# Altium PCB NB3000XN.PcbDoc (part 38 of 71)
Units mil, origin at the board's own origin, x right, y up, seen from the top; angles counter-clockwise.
Board outline 9527.56 x 6929.77 mil, 6 copper layers (Top Layer, GND+SHIELD, MidLayer1, MidLayer2, P2 - 3V3+5V0, Bottom Layer), stack 62.375 mil thick; 832 components, 1027 nets, 4655 pads, 4981 vias.
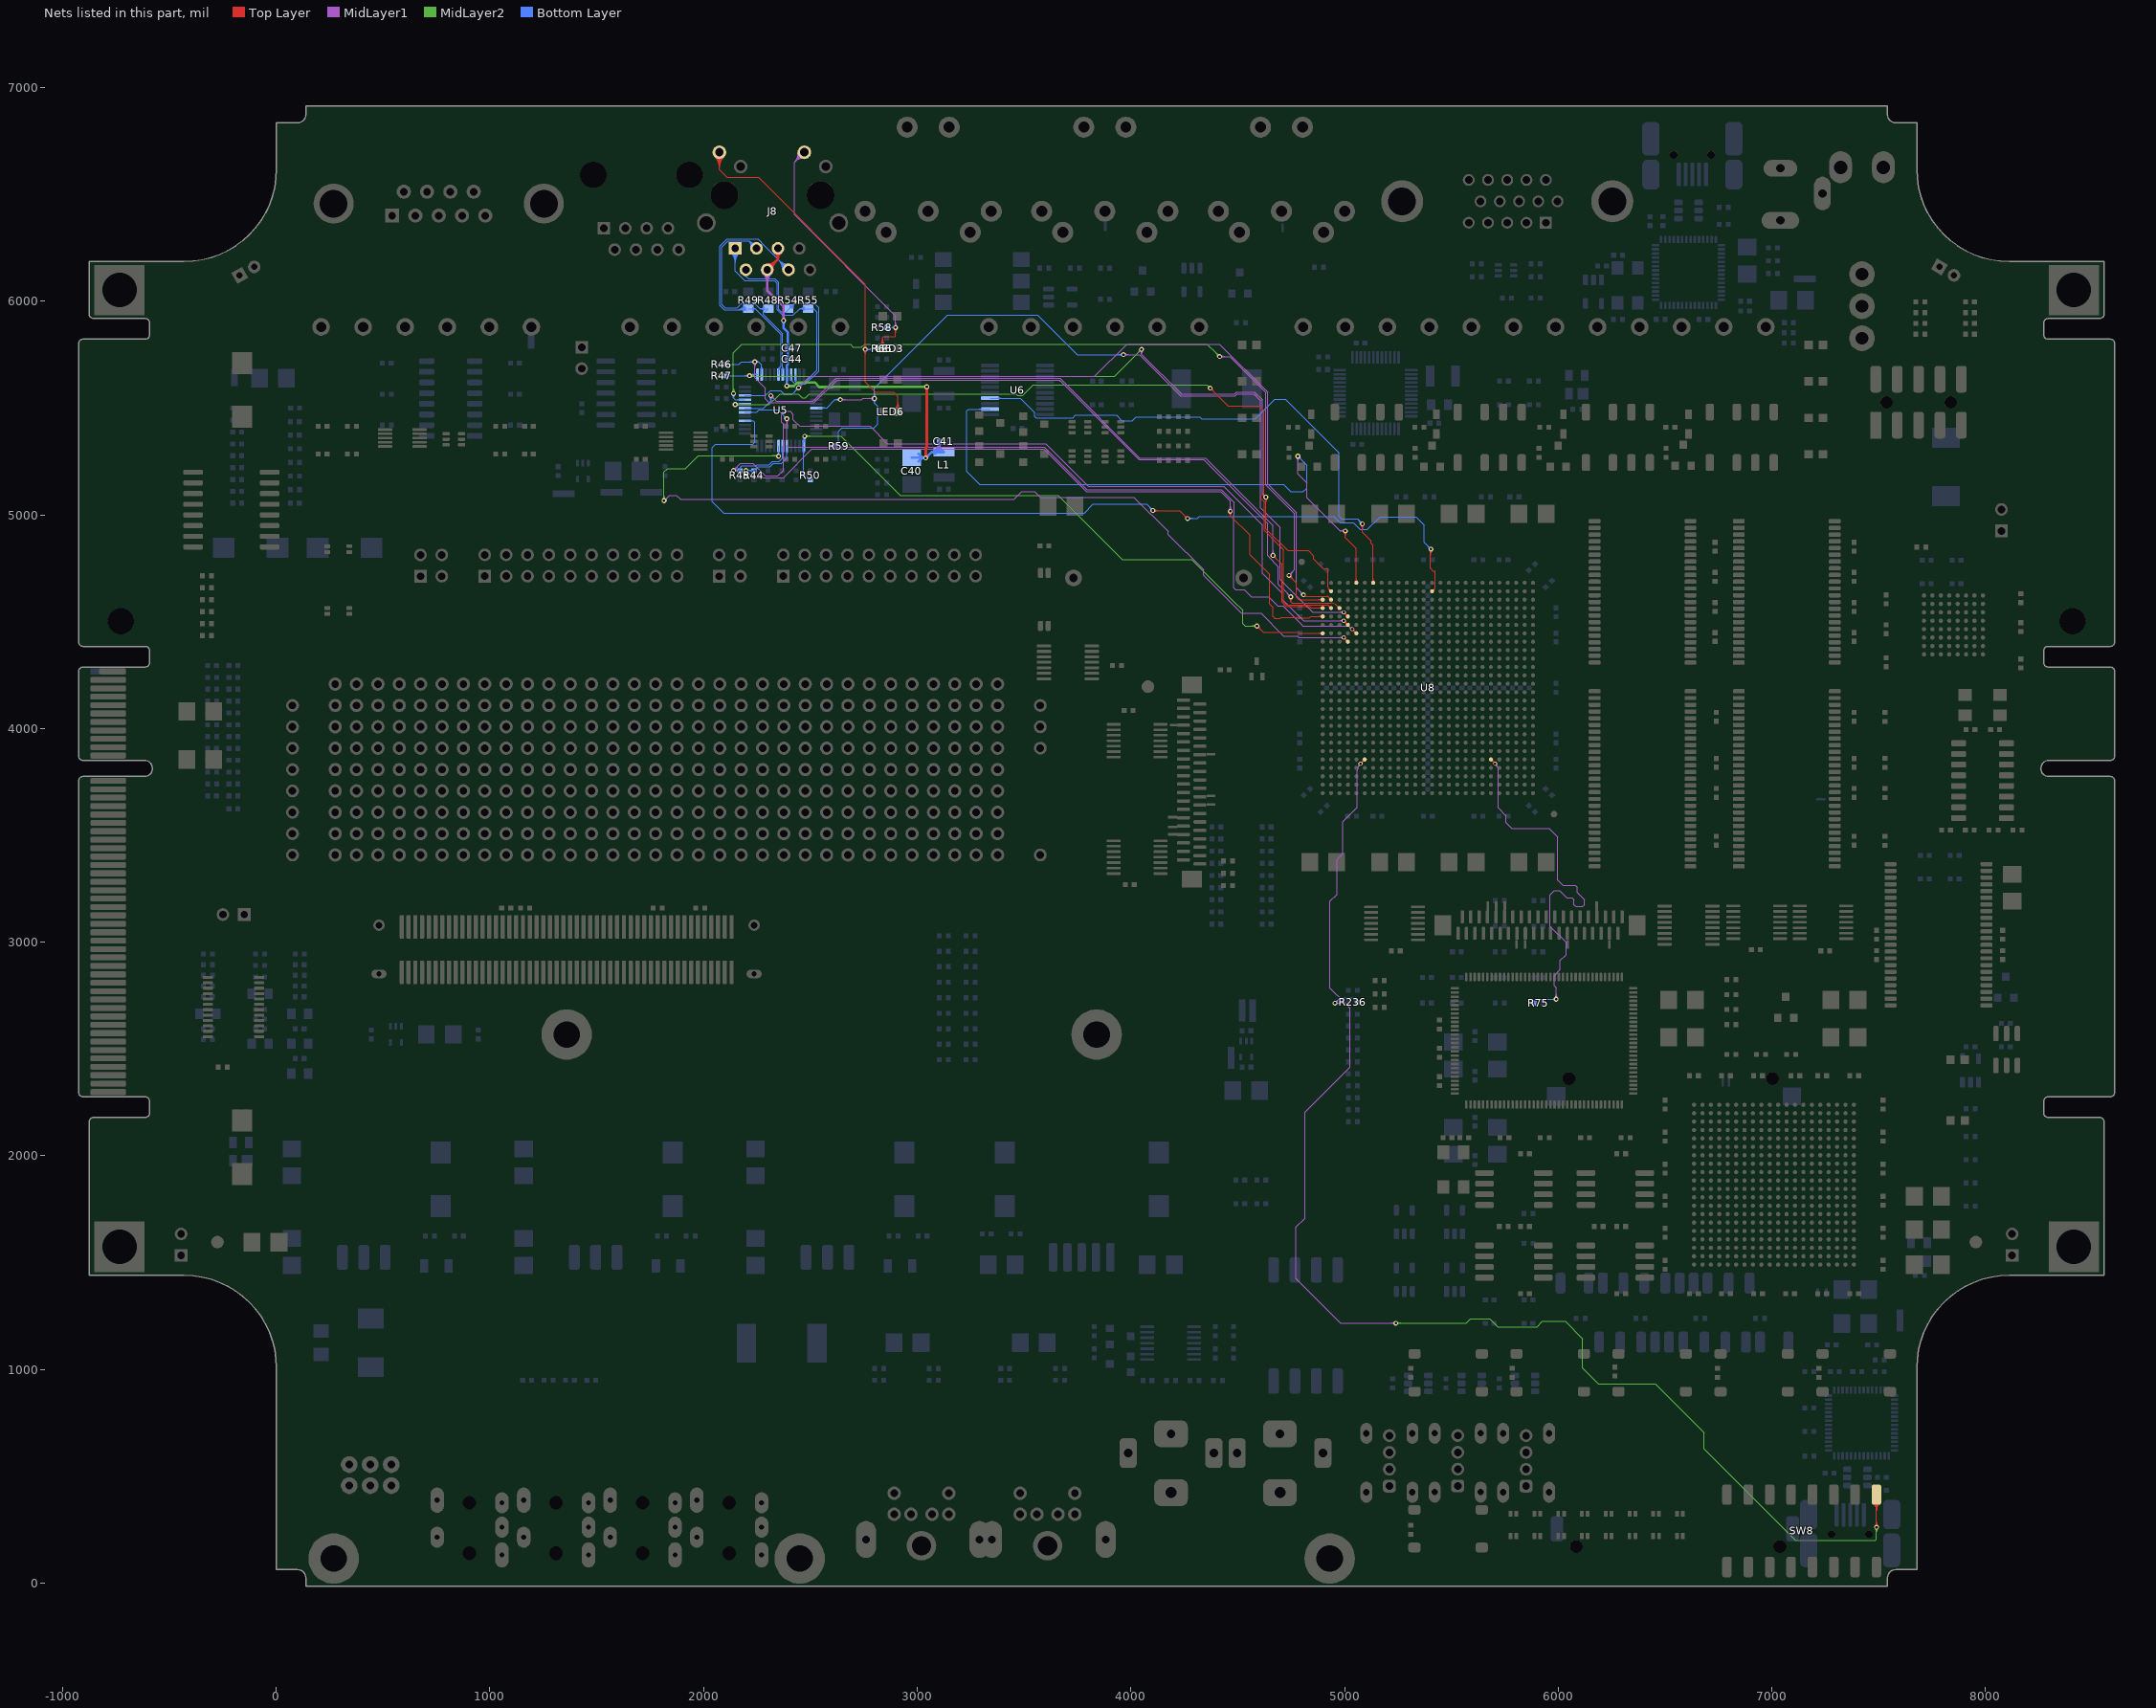
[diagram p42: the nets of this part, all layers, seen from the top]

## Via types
v1: diameter 23, hole 11.81, Top Layer to Bottom Layer, 3672 vias
v2: diameter 26, hole 11.81, Top Layer to Bottom Layer, 461 vias
v3: diameter 19, hole 11.81, Top Layer to Bottom Layer, tented both sides, 396 vias
v4: diameter 23.62, hole 11.81, Top Layer to Bottom Layer, 288 vias
v5: diameter 20, hole 11.81, Top Layer to Bottom Layer, 91 vias
v6: diameter 23, hole 11.81, Top Layer to Bottom Layer, tented both sides, 50 vias
v7: diameter 31, hole 11.81, Top Layer to Bottom Layer, 15 vias
v8: diameter 27.56, hole 11.81, Top Layer to Bottom Layer, tented both sides, 4 vias
v9: diameter 29, hole 11.81, Top Layer to Bottom Layer, 3 vias
v10: diameter 21, hole 11.81, Top Layer to Bottom Layer, 1 vias

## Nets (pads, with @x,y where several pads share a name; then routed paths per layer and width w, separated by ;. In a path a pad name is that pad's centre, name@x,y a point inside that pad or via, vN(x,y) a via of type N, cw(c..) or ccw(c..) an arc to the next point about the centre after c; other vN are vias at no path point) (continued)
DIPSW.D7: R236.1 SW8.9 U8.AB6 | length 7106.8
  Top Layer w4: v3(5075.04,3835.67) U8.AB6@5094.72,3855.35 ; U8.AB6@5087.22,3855.35 cw(c5069.12,3855.35) 5081.92,3842.55 cw(c5094.72,3829.75) U8.AB6@5094.72,3847.85 ; U8.AB6@5087.38,3855.35 cw(c5069.66,3855.35) 5082.19,3842.82 cw(c5094.72,3830.29) U8.AB6@5094.72,3848.01 ; SW8.9@7475.69,374.19 cw(c7441.13,339.63) 7490,339.63 cw(c7538.87,339.63) SW8.9@7504.31,374.19 ; SW8.9@7478.51,377.02 cw(c7450.78,349.29) 7490,349.29 cw(c7529.22,349.29) SW8.9@7501.49,377.02 ; SW8.9@7481.34,379.85 cw(c7460.44,358.94) 7490,358.94 cw(c7519.56,358.94) SW8.9@7498.66,379.85 ; v1@7483.47,268.43 ccw(c7467.71,284.18) 7490,284.18 ; v1@7486.3,265.6 ccw(c7477.37,274.53) 7490,274.53 ; 7490,275.44 ccw(c7503.93,275.44) v1@7494.08,265.6 ; 7490,285.1 ccw(c7513.58,285.1) v1@7496.91,268.43 ; SW8.9@7490,414.29 7490,273.23 7490.19,273.04 v1(7490.19,261.71) ; 5087.84,3848.47 cw(c5075.04,3861.28) 5075.04,3843.17 ccw(c5075.04,3861.28) 5087.84,3848.47 ; 5087.84,3848.47 ccw(c5100.65,3835.67) 5082.54,3835.67 cw(c5100.65,3835.67) 5087.84,3848.47
  MidLayer1 w4: v1(4955,2715) 5002.23,2715 ; v1@4958.89,2711.11 cw(c4968.28,2701.72) 4968.28,2715 cw(c4968.28,2728.28) v1@4958.89,2718.89 ; v1@4961.72,2708.28 cw(c4977.93,2692.06) 4977.93,2715 cw(c4977.93,2737.93) v1@4961.72,2721.72 ; 5064.62,3820.81 ccw(c5092.66,3803.16) 5059.53,3802.99 5059.53,3718.62 5059.53,3670 5059.53,3660 5059.53,3630.7 4992.19,3563.35 4992.19,3413.69 4964.86,3386.36 4964.86,3224.71 4931.86,3191.71 4931.86,2785.37 5002.23,2715 ; v3@5067.65,3834.37 cw(c5049.82,3831.22) 5064.65,3820.84 cw(c5079.49,3810.45) v3@5076.34,3828.28 ; v1@5233.47,1209.99 ccw(c5217.26,1193.77) 5217.26,1216.71 ccw(c5217.26,1239.64) v1@5233.47,1223.43 ; v1@5236.3,1212.82 ccw(c5226.91,1203.43) 5226.91,1216.71 ccw(c5226.91,1229.99) v1@5236.3,1220.6 ; v1(5240.19,1216.71) 4981.86,1216.71 4773.52,1425.04 4773.52,1666.71 4815.19,1708.37 4815.19,2204.71 5025.52,2415.04 5025.52,2691.71 5002.23,2715
  MidLayer2 w4: v1(5240.19,1216.71) 5570.14,1216.71 5590.72,1237.29 5680.32,1237.29 5717.39,1200.21 5901.32,1200.21 5926.31,1225.21 6032.42,1225.21 6113.36,1144.27 6113.36,1007.23 6187.7,932.88 6193.46,932.88 6193.96,933.37 6370,933.37 ; v1@5244.08,1212.82 cw(c5253.47,1203.43) 5253.47,1216.71 cw(c5253.47,1229.99) v1@5244.08,1220.6 ; v1@5246.91,1209.99 cw(c5263.13,1193.77) 5263.13,1216.71 cw(c5263.13,1239.64) v1@5246.91,1223.43 ; 6370,933.71 6454.98,933.71 6683.77,704.91 6683.77,627.79 7111.52,200.04 7485.04,200.04 7490.19,205.19 v1(7490.19,261.71) ; v1@7484,254.5 cw(c7472.46,241.04) 7490.19,241.04 cw(c7507.92,241.04) v1@7496.38,254.5 ; v1@7486.61,257.53 cw(c7479.93,249.74) 7490.19,249.74 cw(c7500.45,249.74) v1@7493.77,257.53
  Bottom Layer w4: v1(4955,2715) 4980,2740 5040.27,2740 R236.1@5061.18,2719.09 ; v1@4955,2720.5 ccw(c4955,2733.78) 4964.39,2724.39 ccw(c4973.78,2715) v1@4960.5,2715 ; v1@4955,2724.5 ccw(c4955,2747.43) 4971.22,2731.22 ccw(c4987.43,2715) v1@4964.5,2715 ; 5044.43,2735.84 ccw(c5061.18,2752.59) R236.1@5061.18,2728.9 ; 5045.62,2734.65 cw(c5030.55,2719.58) R236.1@5051.86,2719.58 ; R236.1@5051.26,2729.01 ccw(c5061.18,2738.93) R236.1@5061.18,2724.9 ; R236.1@5052.45,2727.82 cw(c5044.21,2719.58) R236.1@5055.86,2719.58
DONE: R75.2 U8.AB21 | length 2109.8
  Top Layer w4: U8.AB21@5685.28,3847.85 cw(c5685.28,3829.75) 5698.08,3842.55 cw(c5710.88,3855.35) U8.AB21@5692.78,3855.35 ; U8.AB21@5685.28,3848.01 cw(c5685.28,3830.29) 5697.81,3842.82 cw(c5710.34,3855.35) U8.AB21@5692.62,3855.35 ; U8.AB21@5685.28,3855.35 v3(5704.96,3835.67) ; 5692.16,3848.47 cw(c5679.35,3835.67) 5697.46,3835.67 ccw(c5679.35,3835.67) 5692.16,3848.47 ; 5692.16,3848.47 ccw(c5704.96,3861.28) 5704.96,3843.17 cw(c5704.96,3861.28) 5692.16,3848.47
  MidLayer1 w4: v3@5703.66,3828.28 cw(c5700.51,3810.45) 5715.35,3820.84 cw(c5730.18,3831.22) v3@5712.35,3834.37 ; 5715.38,3820.81 cw(c5687.34,3803.16) 5720.47,3802.99 5720.47,3718.62 5720.47,3670 5720.47,3660 5720.47,3628.06 5756.52,3592 5756.52,3559.98 5783.13,3533.37 5956.86,3533.37 5998.52,3491.71 5998.52,3291.29 6023.1,3266.71 6080.86,3266.71 6089.19,3258.37 6089.19,3233.37 6123.52,3199.04 6123.52,3175.04 6115.19,3166.71 6081.86,3166.71 6073.52,3175.04 6073.52,3200.04 6065.19,3208.37 6040.19,3208.37 6006.86,3241.71 5981.86,3241.71 5962.52,3222.37 5962.52,3074.73 6037.81,2999.44 6037.81,2942.31 6009.19,2913.69 6009.19,2871.37 5981.86,2844.04 5981.86,2795 5990.19,2786.67 v1(5990.19,2733.37) ; v1@5983.47,2740.09 ccw(c5967.26,2756.31) 5990.19,2756.31 ccw(c6013.13,2756.31) v1@5996.91,2740.09 ; v1@5986.3,2737.26 ccw(c5976.91,2746.65) 5990.19,2746.65 ccw(c6003.47,2746.65) v1@5994.08,2737.26
  Bottom Layer w4: R75.2@5885.82,2716.71 R75.2@5885.82,2715 5904.19,2733.37 v1(5990.19,2733.37) ; R75.2@5885.82,2720.81 ccw(c5885.82,2734.84) R75.2@5895.74,2724.92 ; R75.2@5885.82,2724.81 ccw(c5885.82,2748.5) 5902.57,2731.75 ; R75.2@5891.14,2715.49 cw(c5902.79,2715.49) R75.2@5894.55,2723.73 ; R75.2@5895.14,2715.49 cw(c5916.45,2715.49) 5901.38,2730.56
ETH#.ACT_A: J8.9 LED6.1 R66.2 | length 2525.6
  Top Layer w4: J8.9@2052.85,6676.36 cw(c2001.82,6625.33) 2073.98,6625.33 cw(c2146.14,6625.33) J8.9@2095.12,6676.36 ; J8.9@2055.68,6679.18 cw(c2011.48,6634.99) 2073.98,6634.99 cw(c2136.49,6634.99) J8.9@2092.29,6679.18 ; J8.9@2058.51,6682.01 cw(c2021.14,6644.64) 2073.98,6644.64 cw(c2126.83,6644.64) J8.9@2089.46,6682.01 ; J8.9@2061.33,6684.84 cw(c2030.79,6654.3) 2073.98,6654.3 cw(c2117.17,6654.3) J8.9@2086.63,6684.84 ; J8.9@2064.16,6687.67 cw(c2040.45,6663.96) 2073.98,6663.96 cw(c2107.52,6663.96) J8.9@2083.81,6687.67 ; J8.9@2073.98,6697.49 2073.98,6616.02 2110,6580 2256.9,6580 2756.86,6080.04 v1(2756.86,5775.04) 2756.86,5623.14 2805,5575 2890,5575 2909.01,5555.99 2909.01,5509.15 ; v1@2750.14,5768.32 cw(c2733.92,5752.11) 2756.86,5752.11 cw(c2779.79,5752.11) v1@2763.57,5768.32 ; v1@2750.14,5781.76 ccw(c2733.92,5797.98) 2756.86,5797.98 ccw(c2779.79,5797.98) v1@2763.57,5781.76 ; v1@2752.97,5771.15 cw(c2743.58,5761.76) 2756.86,5761.76 cw(c2770.14,5761.76) v1@2760.75,5771.15 ; v1@2752.97,5778.93 ccw(c2743.58,5788.32) 2756.86,5788.32 ccw(c2770.14,5788.32) v1@2760.75,5778.93 ; LED6.1@2896.51,5495.97 ccw(c2866.32,5526.16) 2909.01,5526.16 ccw(c2951.71,5526.16) LED6.1@2921.52,5495.97 ; LED6.1@2899.34,5493.15 ccw(c2875.97,5516.51) 2909.01,5516.51 ccw(c2942.05,5516.51) LED6.1@2918.69,5493.15 ; LED6.1@2902.16,5490.32 ccw(c2885.63,5506.85) 2909.01,5506.85 ccw(c2932.39,5506.85) LED6.1@2915.86,5490.32
  Bottom Layer w4: v1(2756.86,5775.04) 2779.86,5775.04 2783.82,5779 R66.2@2813.82,5779 ; v1@2760.75,5771.15 cw(c2770.14,5761.76) 2770.14,5775.04 cw(c2770.14,5788.32) v1@2760.75,5778.93 ; v1@2763.57,5768.32 cw(c2779.79,5752.11) 2779.79,5775.04 cw(c2779.79,5797.98) v1@2763.57,5781.76 ; R66.2@2807.23,5772.41 ccw(c2791.32,5756.5) 2791.32,5779 ccw(c2791.32,5801.5) R66.2@2807.23,5785.59 ; R66.2@2810.06,5775.24 ccw(c2800.98,5766.16) 2800.98,5779 ccw(c2800.98,5791.84) R66.2@2810.06,5782.76
ETH#.LINK_K: J8.11 LED3.2 R58.2 | length 1895
  Top Layer w4: LED3.2@2825.56,5792.51 ccw(c2795.37,5822.7) 2838.07,5822.7 ccw(c2880.77,5822.7) LED3.2@2850.58,5792.51 ; LED3.2@2828.39,5789.68 ccw(c2805.03,5813.04) 2838.07,5813.04 ccw(c2871.11,5813.04) LED3.2@2847.75,5789.68 ; LED3.2@2831.22,5786.85 ccw(c2814.69,5803.38) 2838.07,5803.38 ccw(c2861.45,5803.38) LED3.2@2844.92,5786.85 ; LED3.2@2838.07,5780 2838.07,5830.03 2843.04,5835 2896.57,5835 2898.86,5837.29 v1(2898.86,5876.71) ; v1@2892.14,5869.99 cw(c2875.92,5853.77) 2898.86,5853.77 cw(c2921.79,5853.77) v1@2905.57,5869.99 ; v1@2894.97,5872.82 cw(c2885.58,5863.43) 2898.86,5863.43 cw(c2912.14,5863.43) v1@2902.75,5872.82
  MidLayer1 w4: J8.11@2442.18,6695.71 cw(c2383.28,6692.2) 2425,6650.48 ; J8.11@2446.17,6695.95 cw(c2395.16,6692.91) 2431.29,6656.77 cw(c2467.43,6620.63) J8.11@2470.47,6671.65 ; J8.11@2450.16,6696.19 cw(c2407.03,6693.62) 2437.59,6663.06 cw(c2468.14,6632.51) J8.11@2470.71,6675.64 ; J8.11@2454.16,6696.43 cw(c2418.91,6694.32) 2443.88,6669.35 cw(c2468.85,6644.38) J8.11@2470.95,6679.63 ; J8.11@2470.24,6667.65 ccw(c2466.72,6608.76) 2425,6650.48 ; J8.11@2472.02,6697.49 2425,6650.48 ; v1@2892.14,5883.43 ccw(c2875.92,5899.64) 2898.86,5899.64 ccw(c2921.79,5899.64) v1@2905.57,5883.43 ; v1@2894.97,5880.6 ccw(c2885.58,5889.99) 2898.86,5889.99 ccw(c2912.14,5889.99) v1@2902.75,5880.6 ; v1(2898.86,5876.71) 2898.86,5931.14 2425,6405 2425,6650.48
  Bottom Layer w4: R58.2@2856.18,5877 2882.57,5877 2882.86,5876.71 ; R58.2@2859.94,5873.24 cw(c2869.02,5864.16) 2869.02,5877 cw(c2869.02,5889.84) R58.2@2859.94,5880.76 ; R58.2@2862.77,5870.41 cw(c2878.68,5854.5) 2878.68,5877 cw(c2878.68,5899.5) R58.2@2862.77,5883.59 ; v1@2890.52,5872.16 ccw(c2882.86,5867.98) 2882.86,5876.71 ; v1@2890.52,5881.26 cw(c2882.86,5885.43) 2882.86,5876.71 ; v1(2898.86,5876.71) 2882.86,5876.71
ETH#.RX_CT: C40.1 C41.2 C44.1 C47.2 J8.4 J8.5 L1.1 U5.32 | length 2667.9
  Top Layer w12: J8.4@2298,6147.49 2348,6197.49 ; J8.4@2298,6171.02 ccw(c2298,6227.82) 2338.16,6187.66 ccw(c2378.33,6147.49) J8.4@2321.53,6147.49 ; J8.5@2333,6229.36 cw(c2306.64,6197.49) 2348,6197.49 ; J8.5@2348,6247.49 2348,6197.49 ; J8.5@2363,6229.36 ccw(c2389.36,6197.49) 2348,6197.49 ; v1@3036.3,5270.6 ccw(c3026.91,5279.99) 3040.19,5279.99 ccw(c3053.47,5279.99) v1@3044.08,5270.6 ; v1(3040.19,5266.71) 3040.19,5315.19 3045,5320 v4(3045,5600) ; v4@3040.89,5595.89 cw(c3030.97,5585.97) 3045,5585.97 cw(c3059.03,5585.97) v4@3049.11,5595.89
  MidLayer1 w12: J8.4@2281.36,6130.85 cw(c2241.2,6090.69) 2298,6090.69 cw(c2354.8,6090.69) J8.4@2314.64,6130.85 ; J8.4@2298,6147.49 2298,6051.28 2375,5974.28 v4(2375,5910) ; v4@2370.89,5914.11 ccw(c2360.97,5924.03) 2375,5924.03 ccw(c2389.03,5924.03) v4@2379.11,5914.11
  MidLayer2 w12: v1(2390.19,5603.37) 2422.97,5603.37 2436.09,5616.5 2436.5,5616.5 2440,5620 2520,5620 2541.81,5598.19 2603.19,5598.19 2605,5600 v4(3045,5600) ; v1@2394.08,5599.49 cw(c2403.47,5590.1) 2403.47,5603.37 cw(c2403.47,5616.65) v1@2394.08,5607.26 ; v4@3040.89,5595.89 ccw(c3030.97,5585.97) 3030.97,5600 ccw(c3030.97,5614.03) v4@3040.89,5604.11
  Bottom Layer w12: v4@2370.89,5905.89 cw(c2360.97,5895.97) 2375,5895.97 cw(c2389.03,5895.97) v4@2379.11,5905.89 ; v4(2375,5910) 2375,5875 2394.33,5855.67 C47.2@2394.33,5780 C44.1@2394.33,5730 ; v1@2386.3,5607.26 ccw(c2376.42,5617.14) 2390.39,5617.14 ; v1(2390.19,5603.37) 2390.39,5603.58 U5.32@2390.39,5657.32 2390.39,5701.06 2394.33,5705 C44.1@2394.33,5730 ; C44.1@2390.22,5725.89 cw(c2380.3,5715.97) 2394.33,5715.97 cw(c2408.36,5715.97) C44.1@2398.44,5725.89 ; C44.1@2390.22,5734.11 ccw(c2380.3,5744.03) 2394.33,5744.03 ccw(c2408.36,5744.03) C44.1@2398.44,5734.11 ; C47.2@2390.22,5775.89 cw(c2380.3,5765.97) 2394.33,5765.97 cw(c2408.36,5765.97) C47.2@2398.44,5775.89 ; C47.2@2390.22,5784.11 ccw(c2380.3,5794.03) 2394.33,5794.03 ccw(c2408.36,5794.03) C47.2@2398.44,5784.11 ; 2390.39,5616.16 ccw(c2402.98,5616.16) v1@2394.08,5607.26 ; C40.1@2975,5267.99 v1@3038.91,5267.99 ; C40.1@3007.29,5250.4 cw(c3038.9,5230.8) v1@3038.9,5267.99 ; C40.1@3007.29,5285.58 ccw(c3038.9,5305.19) v1@3038.9,5267.99 ; 3023.81,5267.99 cw(c3023.81,5250.33) v1@3036.3,5262.82 ; v1@3040.19,5272.21 ccw(c3040.19,5285.49) 3049.58,5276.1 ccw(c3058.97,5266.71) v1@3045.69,5266.71 ; L1.1@3084.66,5285.67 ccw(c3067.54,5272.39) 3067.54,5294.06 ; L1.1@3084.66,5302.44 cw(c3067.54,5315.72) 3067.54,5294.06 ; L1.1@3086.6,5304.47 ccw(c3052.64,5344.33) C41.2@3105,5344.33 ; L1.1@3094.38,5295.34 ccw(c3074.78,5318.34) 3105,5318.34 ; C41.2@3100.22,5340.89 cw(c3088.69,5329.36) 3105,5329.36 ; C41.2@3104.33,5345 C41.2@3105,5344.33 ; 3105,5332.59 cw(c3116.74,5332.59) C41.2@3108.44,5340.89 ; v1@3038.91,5267.99 v1(3040.19,5266.71) 3067.54,5294.05 ; 3067.54,5294.06 L1.1@3125,5294.06 3105,5314.06 C41.2@3105,5344.33
ETH#.RX_N: J8.6 R49.1 U5.30 | length 1788
  Bottom Layer w4: 2148.79,5960 ccw(c2148.79,6021.92) R49.1@2192.57,5978.14 ; 2158.45,5960 ccw(c2158.45,6012.26) R49.1@2195.4,5975.31 ; 2168.11,5960 ccw(c2168.11,6002.6) R49.1@2198.23,5972.48 ; 2175.98,5960 cw(c2175.98,5936.53) R49.1@2192.57,5953.12 ; 2177.76,5960 ccw(c2177.76,5992.95) R49.1@2201.06,5969.65 ; R49.1@2185.63,5960 cw(c2185.63,5946.18) R49.1@2195.4,5955.95 ; R49.1@2206.12,5960 2097,5960 2077,5980 2077,6257 2111.02,6291.02 2254.72,6291.02 2283.53,6262.21 2283.53,6261.72 2397.76,6147.49 J8.6@2398,6147.49 ; R49.1@2211.75,5963.88 2243.11,5963.88 ; R49.1@2226.65,5958.57 cw(c2236.04,5952.93) 2236.04,5963.88 ; R49.1@2227.71,5970.5 ccw(c2237.31,5974.15) 2237.31,5963.88 ; R49.1@2230.07,5956.51 cw(c2243.11,5948.67) 2243.11,5963.88 ; R49.1@2231.45,5971.92 ccw(c2243.11,5976.36) 2243.11,5963.88 ; 2350.59,6194.66 ccw(c2398,6242.06) J8.6@2398,6175.02 ; U5.30@2351.02,5657.32 2351.02,5686.02 2362.71,5697.71 2362.71,5844.28 2243.11,5963.88 ; U5.30@2351.02,5680.85 cw(c2363.51,5680.85) 2354.68,5689.68 ; 2351.18,6194.07 cw(c2304.6,6147.49) J8.6@2370.47,6147.49 ; U5.30@2355.02,5680.85 cw(c2377.17,5680.85) 2361.51,5696.51 ; 2357.42,6187.83 ccw(c2398,6228.41) J8.6@2398,6171.02 ; 2358.01,6187.24 cw(c2318.26,6147.49) J8.6@2374.47,6147.49 ; 2364.25,6181 ccw(c2398,6214.75) J8.6@2398,6167.02 ; 2364.84,6180.41 cw(c2331.92,6147.49) J8.6@2378.47,6147.49 ; 2371.08,6174.17 ccw(c2398,6201.09) J8.6@2398,6163.02 ; 2371.67,6173.58 cw(c2345.57,6147.49) J8.6@2382.47,6147.49
ETH#.RX_P: J8.3 R48.1 U5.31 | length 1321.8
  Bottom Layer w4: J8.3@2221.12,6253.42 ccw(c2189.79,6260.33) 2212.47,6283.02 ; J8.3@2225.02,6252.56 ccw(c2198.25,6258.46) 2217.64,6277.85 ccw(c2237.03,6297.25) J8.3@2242.93,6270.47 ; J8.3@2228.93,6251.7 ccw(c2206.7,6256.6) 2222.8,6272.69 ccw(c2238.89,6288.79) J8.3@2243.79,6266.56 ; J8.3@2242.07,6274.37 cw(c2235.16,6305.7) 2212.47,6283.02 ; J8.3@2248,6247.49 2212.47,6283.02 ; R48.1@2283.75,5955.7 ccw(c2265,5942.96) 2265,5965.63 ; R48.1@2283.75,5975.56 cw(c2265,5988.3) 2265,5965.63 ; R48.1@2287.06,5957.94 ccw(c2272.55,5948.09) 2272.55,5965.63 ccw(c2272.55,5983.17) R48.1@2287.06,5973.32 ; U5.31@2367.88,5683.68 ccw(c2361.05,5690.51) 2370.71,5690.51 ccw(c2380.37,5690.51) U5.31@2373.54,5683.68 ; U5.31@2370.71,5657.32 2370.71,5847.6 2280,5938.31 2280,5950 2287.68,5950 R48.1@2303.31,5965.63 2265,5965.63 ; 2212.47,6283.02 2114.33,6283.02 2085,6253.69 2085,5985 2100,5970 2157.79,5970 2180,5992.21 2238.42,5992.21 2265,5965.63
ETH#.TX_N: J8.2 R54.2 U5.33 | length 1158.1
  Bottom Layer w4: J8.2@2198,6147.49 2198,6117 2210,6105 2335,6105 2353,6087 2353,5963.31 2366.31,5950 2385.94,5950 2399.13,5963.19 2427.25,5991.31 ; R54.2@2402.77,5975.25 ccw(c2404.64,5990.67) R54.2@2415.62,5979.68 ; R54.2@2403.25,5979.22 ccw(c2405.89,6001.05) 2421.44,5985.5 ; R54.2@2403.73,5983.19 ccw(c2407.14,6011.43) 2427.25,5991.31 ; U5.33@2410.08,5629.8 cw(c2410.08,5625.09) U5.33@2413.41,5628.42 ; U5.33@2410.08,5657.32 2410.08,5631.74 2428.94,5612.88 2478.26,5612.88 2540,5674.62 2540,5968.41 2517.09,5991.31 2427.25,5991.31 ; R54.2@2411.23,5966.82 cw(c2426.67,5968.72) R54.2@2415.67,5979.73 ; U5.33@2414.08,5633.8 ccw(c2428.69,5633.8) 2418.36,5623.47 ; R54.2@2415.2,5967.31 cw(c2436.98,5970) 2421.46,5985.52 ; R54.2@2419.17,5967.8 cw(c2447.3,5971.27) 2427.25,5991.31
ETH#.TX_P: J8.1 R55.2 U5.34 | length 1538.5
  Bottom Layer w4: J8.1@2128.54,6228.03 cw(c2081.54,6181.03) 2148,6181.03 cw(c2214.46,6181.03) J8.1@2167.46,6228.03 ; J8.1@2131.36,6230.85 cw(c2091.2,6190.69) 2148,6190.69 cw(c2204.8,6190.69) J8.1@2164.64,6230.85 ; J8.1@2134.19,6233.68 cw(c2100.86,6200.35) 2148,6200.35 cw(c2195.14,6200.35) J8.1@2161.81,6233.68 ; J8.1@2137.02,6236.51 cw(c2110.51,6210) 2148,6210 cw(c2185.49,6210) J8.1@2158.98,6236.51 ; J8.1@2148.24,6247.49 J8.1@2148,6247.49 2148,6142 2193,6097 2331.69,6097 2345,6083.69 2345,5960 2370,5935 2420,5935 2450.63,5965.63 ; U5.34@2426.94,5630.97 cw(c2420.11,5624.14) 2429.76,5624.14 cw(c2439.42,5624.14) U5.34@2432.59,5630.97 ; U5.34@2429.76,5657.32 2429.76,5623.37 2431.43,5621.71 2432.26,5620.88 2474.95,5620.88 2531.86,5677.79 2531.86,5950.04 2516.27,5965.63 ; R55.2@2470.71,5955.32 ccw(c2450.63,5940.92) 2450.63,5965.63 ; R55.2@2470.71,5975.94 cw(c2450.63,5990.33) 2450.63,5965.63 ; R55.2@2473.96,5957.65 ccw(c2458.42,5946.51) 2458.42,5965.63 ccw(c2458.42,5984.75) R55.2@2473.96,5973.61 ; R55.2@2488.13,5967.5 R55.2@2490,5965.63 ; R55.2@2512.3,5962.34 cw(c2516.27,5961.59) 2516.27,5965.63 ; R55.2@2512.3,5968.92 ccw(c2516.27,5969.67) 2516.27,5965.63 ; 2450.63,5965.63 R55.2@2490,5965.63 ; R55.2@2490,5965.63 2516.27,5965.63
ETH.E_COL: R50.1 U5.1 U8.G1 | length 3475.1
  Top Layer w4: v1@4590,4470.5 cw(c4590,4447.56) 4606.22,4463.78 cw(c4622.43,4480) v1@4599.5,4480 ; v1@4590,4474.5 cw(c4590,4461.22) 4599.39,4470.61 cw(c4608.78,4480) v1@4595.5,4480 ; v1(4590,4480) 4620.13,4449.87 4780.64,4449.87 4784.6,4445.91 4860,4445.91 4870,4445.91 U8.G1@4897.87,4445.91 ; U8.G1@4892.57,4440.6 ccw(c4879.77,4427.8) 4879.77,4445.91 ccw(c4879.77,4464.01) U8.G1@4892.57,4451.21 ; 4880.15,4445.91 ccw(c4880.15,4463.63) 4892.68,4451.1 cw(c4880.15,4463.63) 4880.15,4445.91 ; 4880.15,4445.91 cw(c4880.15,4428.18) 4892.68,4440.71 ccw(c4880.15,4428.18) 4880.15,4445.91
  MidLayer2 w4: v1(2473.52,5368.37) 2643.88,5368.37 2920.54,5091.71 3659.84,5091.71 3960.17,4791.37 4285.17,4791.37 4479.62,4596.92 4523.19,4553.35 4523.19,4491.81 4535,4480 v1(4590,4480) ; v1@2477.41,5364.49 cw(c2486.8,5355.1) 2486.8,5368.37 cw(c2486.8,5381.65) v1@2477.41,5372.26 ; v1@2480.24,5361.66 cw(c2496.46,5345.44) 2496.46,5368.37 cw(c2496.46,5391.31) v1@2480.24,5375.09 ; v1@4583.28,4473.28 ccw(c4567.06,4457.06) 4567.06,4480 ccw(c4567.06,4502.93) v1@4583.28,4486.72 ; v1@4586.11,4476.11 ccw(c4576.72,4466.72) 4576.72,4480 ccw(c4576.72,4493.28) v1@4586.11,4483.89
  Bottom Layer w4: U5.1@2466.31,5296.32 cw(c2459.48,5289.49) 2469.13,5289.49 cw(c2478.79,5289.49) U5.1@2471.96,5296.32 ; U5.1@2466.31,5349.03 ccw(c2448.88,5366.46) v1@2473.52,5366.46 ; v1@2466.81,5361.66 cw(c2450.59,5345.44) 2473.52,5345.44 cw(c2496.46,5345.44) v1@2480.24,5361.66 ; U5.1@2469.13,5346.2 ccw(c2458.53,5356.8) 2473.52,5356.8 ; v1@2469.64,5364.49 cw(c2460.25,5355.1) 2473.52,5355.1 cw(c2486.8,5355.1) v1@2477.41,5364.49 ; v1(2473.52,5368.37) 2473.52,5345 2469.13,5340.61 U5.1@2469.13,5322.68 2469.13,5194.69 R50.1@2500,5163.82 ; 2483.25,5180.57 cw(c2466.5,5163.82) R50.1@2490.19,5163.82 ; 2484.44,5179.38 ccw(c2499.51,5194.45) R50.1@2499.51,5173.14 ; R50.1@2490.08,5173.74 cw(c2480.16,5163.82) R50.1@2494.19,5163.82 ; R50.1@2491.27,5172.55 ccw(c2499.51,5180.79) R50.1@2499.51,5169.14
ETH.E_CRS: U6.12 U8.A5 | length 3232.6
  Top Layer w4: v1@4997.14,4918.32 cw(c4980.92,4902.11) 5003.86,4902.11 cw(c5026.79,4902.11) v1@5010.57,4918.32 ; v1@4999.97,4921.15 cw(c4990.58,4911.76) 5003.86,4911.76 cw(c5017.14,4911.76) v1@5007.75,4921.15 ; v1(5003.86,4925.04) 5003.86,4893.67 5030.15,4867.37 5055.35,4842.17 5055.35,4720 5055.35,4710 U8.A5@5055.35,4682.13 ; U8.A5@5050.05,4687.43 ccw(c5037.25,4700.23) 5055.35,4700.23 ccw(c5073.46,4700.23) U8.A5@5060.66,4687.43 ; U8.A5@5050.16,4687.32 ccw(c5037.63,4699.85) 5055.35,4699.85 ccw(c5073.08,4699.85) U8.A5@5060.55,4687.32
  MidLayer1 w4: v1@4775.14,5268.32 cw(c4758.92,5252.11) 4781.86,5252.11 cw(c4804.79,5252.11) v1@4788.57,5268.32 ; v1@4777.97,5271.15 cw(c4768.58,5261.76) 4781.86,5261.76 cw(c4795.14,5261.76) v1@4785.75,5271.15 ; v1(4781.86,5275.04) 4781.86,5191.71 4823.52,5150.04 4823.52,5080.37 4978.86,4925.04 v1(5003.86,4925.04) ; v1@4997.14,4918.32 ccw(c4980.92,4902.11) 4980.92,4925.04 ccw(c4980.92,4947.98) v1@4997.14,4931.76 ; v1@4999.97,4921.15 ccw(c4990.58,4911.76) 4990.58,4925.04 ccw(c4990.58,4938.32) v1@4999.97,4928.93
  Bottom Layer w4: U6.12@3302.75,5490.58 ccw(c3291.04,5478.88) 3291.04,5495.43 ccw(c3291.04,5511.99) U6.12@3302.75,5500.28 ; U6.12@3341.06,5495.43 3239.86,5495.43 3231.86,5487.43 3231.86,5203.14 3292.81,5142.19 4714.71,5142.19 4748.52,5108.37 4806.86,5108.37 4823.52,5125.04 4823.52,5233.37 v1(4781.86,5275.04) ; v1@4781.86,5265.54 cw(c4781.86,5242.61) 4798.07,5258.82 cw(c4814.29,5275.04) v1@4791.36,5275.04 ; v1@4781.86,5269.54 cw(c4781.86,5256.26) 4791.25,5265.65 cw(c4800.64,5275.04) v1@4787.36,5275.04
ETH.E_MDC: R47.1 U5.25 U8.B2 | length 4345.9
  Top Layer w4: v1@4625.14,5076.66 cw(c4608.92,5060.44) 4631.86,5060.44 cw(c4654.79,5060.44) v1@4638.57,5076.66 ; v1@4627.97,5079.49 cw(c4618.58,5070.1) 4631.86,5070.1 cw(c4645.14,5070.1) v1@4635.75,5079.49 ; v1(4631.86,5083.37) 4631.86,4935.04 4733.52,4833.37 4830.19,4833.37 4855.52,4808.04 4855.52,4794.41 4892.25,4757.69 4900.94,4749 4919,4749 4921.74,4746.26 4921.74,4728.2 4921.74,4724.74 4921.74,4720 4921.74,4710 4921.74,4662.47 ; 4921.74,4662.47 ccw(c4931.89,4662.47) 4924.71,4655.29 ; 4921.74,4662.47 ccw(c4931.89,4662.47) 4924.71,4655.29 ; 4924.71,4655.29 ccw(c4937.24,4667.83) 4937.24,4650.1 cw(c4937.24,4667.83) 4924.71,4655.29 ; 4924.71,4655.29 cw(c4912.17,4642.76) 4929.9,4642.76 ccw(c4912.17,4642.76) 4924.71,4655.29
  MidLayer1 w4: v1@4043.14,5768.32 cw(c4026.92,5752.11) 4049.86,5752.11 cw(c4072.79,5752.11) v1@4056.57,5768.32 ; v1@4045.97,5771.15 cw(c4036.58,5761.76) 4049.86,5761.76 cw(c4063.14,5761.76) v1@4053.75,5771.15 ; v1(4049.86,5775.04) 4049.86,5751.69 4236.55,5565 4485,5565 4495,5575 4578.69,5575 4615.19,5538.5 4615.19,5100.04 v1(4631.86,5083.37) ; v1@4622.36,5083.37 ccw(c4599.42,5083.37) 4615.64,5099.59 ccw(c4631.86,5115.81) v1@4631.86,5092.87 ; v1@4626.36,5083.37 ccw(c4613.08,5083.37) 4622.47,5092.76 ccw(c4631.86,5102.15) v1@4631.86,5088.87
  MidLayer2 w4: v1(2215.19,5651.67) 2216.82,5650.04 3924.86,5650.04 v1(4049.86,5775.04) ; v1@2219.08,5655.56 ccw(c2232.39,5668.87) 2232.39,5650.04 ; v1@2221.91,5644.95 cw(c2234.2,5632.66) 2234.2,5650.04 ; v1@2221.91,5658.38 ccw(c2242.05,5678.53) 2242.05,5650.04 ; v1@4040.36,5775.04 cw(c4017.42,5775.04) 4033.64,5758.82 cw(c4049.86,5742.61) v1@4049.86,5765.54 ; v1@4044.36,5775.04 cw(c4031.08,5775.04) 4040.47,5765.65 cw(c4049.86,5756.26) v1@4049.86,5769.54
  Bottom Layer w4: R47.1@2106.18,5651.67 v1(2215.19,5651.67) 2215.19,5651.99 2220.52,5657.32 U5.25@2252.6,5657.32 ; R47.1@2109.94,5647.91 cw(c2119.02,5638.83) 2119.02,5651.67 cw(c2119.02,5664.51) R47.1@2109.94,5655.43 ; R47.1@2112.77,5645.08 cw(c2128.68,5629.17) 2128.68,5651.67 cw(c2128.68,5674.16) R47.1@2112.77,5658.26 ; v1@2208.47,5644.95 ccw(c2192.26,5628.73) 2192.26,5651.67 ccw(c2192.26,5674.6) v1@2208.47,5658.38 ; v1@2211.3,5647.78 ccw(c2201.91,5638.39) 2201.91,5651.67 ccw(c2201.91,5664.94) v1@2211.3,5655.56 ; v1@2216.25,5650.61 cw(c2232.47,5634.39) 2232.47,5657.32 ; v1@2219.08,5647.78 cw(c2242.12,5624.73) 2242.12,5657.32 ; v1@2221.91,5644.95 cw(c2251.78,5615.08) U5.25@2251.78,5657.32 ; U5.25@2249.77,5654.49 ccw(c2242.94,5647.67) 2242.94,5657.32 ccw(c2242.94,5666.98) U5.25@2249.77,5660.15
ETH.E_MDIO: R46.1 U5.26 U8.D3 | length 4233.6
  Top Layer w4: v1@4741.81,4609.99 cw(c4725.59,4593.77) 4748.52,4593.77 cw(c4771.46,4593.77) v1@4755.24,4609.99 ; v1@4744.64,4612.82 cw(c4735.25,4603.43) 4748.52,4603.43 cw(c4761.8,4603.43) v1@4752.41,4612.82 ; v1(4748.52,4616.71) 4748.52,4593.37 ; 4851.26,4587.88 4854.73,4587.88 ; 4748.52,4593.37 4750.19,4591.71 ; 4748.52,4593.37 4750.19,4591.71 ; 4750.19,4591.71 4754.02,4587.88 4854.73,4587.88 ; 4854.73,4587.88 4855.26,4587.88 4860,4587.88 ; 4854.73,4587.88 4860,4587.88 ; 4860,4587.88 4870,4587.88 4873.88,4587.88 4936.73,4587.88 ; 4936.73,4587.88 cw(c4936.73,4549.2) 4964.08,4576.55 ; 4936.73,4587.88 cw(c4936.73,4549.2) 4964.08,4576.55 ; 4964.08,4576.55 ccw(c4976.61,4589.08) 4976.61,4571.36 cw(c4976.61,4589.08) 4964.08,4576.55 ; 4964.08,4576.55 cw(c4951.55,4564.02) 4969.27,4564.02 ccw(c4951.55,4564.02) 4964.08,4576.55
  MidLayer1 w4: v1@2233.47,5709.99 cw(c2217.26,5693.77) 2240.19,5693.77 cw(c2263.13,5693.77) v1@2246.91,5709.99 ; v1@2236.3,5712.82 cw(c2226.91,5703.43) 2240.19,5703.43 cw(c2253.47,5703.43) v1@2244.08,5712.82 ; v1(2240.19,5716.71) 2240.19,5641.71 2248.52,5633.37 ; 3666.31,5630 4037.94,5258.37 4340.19,5258.37 4640.19,4958.37 4640.19,4808.37 4690.19,4758.37 4690.19,4695 4690.19,4683.37 4690.19,4675.04 4722.39,4642.84 v1(4748.52,4616.71) v1@4748.52,4625.04 ; 3679.28,5617.03 3664.31,5632 2624.37,5632 2517.08,5524.71 2308.17,5524.71 2290.19,5542.69 2290.19,5591.71 ; v1@4739.02,4616.71 ccw(c4716.09,4616.71) 4732.31,4632.93 ccw(c4748.52,4649.14) v1@4748.52,4626.21 ; v1@4743.02,4616.71 ccw(c4729.75,4616.71) 4739.14,4626.1 ccw(c4748.52,4635.49) v1@4748.52,4622.21 ; 2248.52,5633.37 2286.02,5595.87 ; 2248.52,5633.37 2286.02,5595.87 ; 2286.02,5595.87 2290.19,5591.71 ; 2286.02,5595.87 2290.19,5591.71
  Bottom Layer w4: R46.1@2106.18,5705 2165,5705 2176.71,5716.71 v1(2240.19,5716.71) 2258.29,5716.71 ; R46.1@2109.94,5701.24 cw(c2119.02,5692.16) 2119.02,5705 cw(c2119.02,5717.84) R46.1@2109.94,5708.76 ; R46.1@2112.77,5698.41 cw(c2128.68,5682.5) 2128.68,5705 cw(c2128.68,5727.5) R46.1@2112.77,5711.59 ; v1@2233.47,5709.99 ccw(c2217.26,5693.77) 2217.26,5716.71 ccw(c2217.26,5739.64) v1@2233.47,5723.43 ; v1@2236.3,5712.82 ccw(c2226.91,5703.43) 2226.91,5716.71 ccw(c2226.91,5729.99) v1@2236.3,5720.6 ; v1@2248.01,5711.31 cw(c2258.29,5704.21) 2258.29,5716.71 ; v1@2248.01,5722.1 ccw(c2258.29,5729.2) 2258.29,5716.71 ; U5.26@2269.45,5683.68 ccw(c2262.63,5690.51) 2272.28,5690.51 ccw(c2281.94,5690.51) U5.26@2275.11,5683.68 ; U5.26@2272.28,5657.32 2272.28,5702.72 2258.29,5716.71
ETH.E_RESETB_E: R59.1 U5.42 U8.E4 | length 4785.1
  Top Layer w4: v3(4996.3,4544.33) U8.E4@5015.98,4524.65 ; U8.E4@5008.48,4524.65 ccw(c4990.38,4524.65) 5003.18,4537.45 ccw(c5015.98,4550.25) U8.E4@5015.98,4532.15 ; U8.E4@5008.64,4524.65 ccw(c4990.92,4524.65) 5003.45,4537.18 ccw(c5015.98,4549.71) U8.E4@5015.98,4531.99 ; 5009.1,4531.53 cw(c5021.91,4544.33) 5003.8,4544.33 ccw(c5021.91,4544.33) 5009.1,4531.53 ; 5009.1,4531.53 ccw(c4996.3,4518.72) 4996.3,4536.83 cw(c4996.3,4518.72) 5009.1,4531.53
  MidLayer1 w4: v4(2640,5540) 2740,5540 2745,5545 v4(2800,5545) ; v4@2644.11,5535.89 cw(c2654.03,5525.97) 2654.03,5540 cw(c2654.03,5554.03) v4@2644.11,5544.11 ; v4@2646.94,5533.06 cw(c2663.69,5516.31) 2663.69,5540 cw(c2663.69,5563.69) v4@2646.94,5546.94 ; v4@2793.06,5538.06 ccw(c2776.31,5521.31) 2776.31,5545 ccw(c2776.31,5568.69) v4@2793.06,5551.94 ; v4@2795.89,5540.89 ccw(c2785.97,5530.97) 2785.97,5545 ccw(c2785.97,5559.03) v4@2795.89,5549.11 ; v1(3965.19,5750.04) 4040.19,5750.04 4199.18,5591.05 4233.23,5557 4488.31,5557 4498.31,5567 4575.37,5567 4606.86,5535.52 4606.86,5033.37 4698.52,4941.71 4698.52,4696.48 4850.67,4544.33 4860,4544.33 4870,4544.33 4918.62,4544.33 v3(4996.3,4544.33) ; v1@3969.08,5746.15 cw(c3978.47,5736.76) 3978.47,5750.04 cw(c3978.47,5763.32) v1@3969.08,5753.93 ; v1@3971.91,5743.32 cw(c3988.13,5727.11) 3988.13,5750.04 cw(c3988.13,5772.98) v1@3971.91,5756.76 ; v3@4991.11,4539.14 ccw(c4978.57,4526.6) 4978.57,4544.33 ccw(c4978.57,4562.06) v3@4991.11,4549.52 ; 4978.19,4544.33 cw(c4978.19,4526.22) 4991,4539.03 ccw(c4978.19,4526.22) 4978.19,4544.33 ; 4978.19,4544.33 ccw(c4978.19,4562.44) 4991,4549.63 cw(c4978.19,4562.44) 4978.19,4544.33
  Bottom Layer w4: U5.42@2540.19,5500.04 2542.15,5502 2577,5502 2615,5540 v4(2640,5540) ; U5.42@2554.54,5497.01 cw(c2566.58,5484.98) 2566.58,5502 ; R59.1@2613.82,5322.5 2632.14,5340.82 2632.14,5391.99 2647.96,5407.81 2732.38,5407.81 2733.81,5406.37 2796.52,5406.37 2815.19,5425.04 2815.19,5508.12 2800,5523.31 ; R59.1@2613.82,5328.31 ccw(c2613.82,5342.34) R59.1@2623.74,5332.42 ; R59.1@2613.82,5332.31 ccw(c2613.82,5356) 2630.57,5339.25 ; R59.1@2619.14,5322.99 cw(c2630.79,5322.99) R59.1@2622.55,5331.23 ; R59.1@2623.14,5322.99 cw(c2644.45,5322.99) 2629.38,5338.06 ; v4@2633.06,5533.06 ccw(c2616.31,5516.31) 2616.31,5540 ccw(c2616.31,5563.69) v4@2633.06,5546.94 ; v4@2635.89,5535.89 ccw(c2625.97,5525.97) 2625.97,5540 ccw(c2625.97,5554.03) v4@2635.89,5544.11 ; v4@2793.06,5551.94 ccw(c2776.31,5568.69) 2800,5568.69 ccw(c2823.69,5568.69) v4@2806.94,5551.94 ; v4@2793.52,5537.63 cw(c2780.94,5523.31) 2800,5523.31 ; v4@2795.89,5549.11 ccw(c2785.97,5559.03) 2800,5559.03 ccw(c2814.03,5559.03) v4@2804.11,5549.11 ; v4@2796.16,5540.64 cw(c2788.71,5532.16) 2800,5532.16 cw(c2811.29,5532.16) v4@2803.84,5540.64 ; v4@2806.48,5537.63 ccw(c2819.06,5523.31) 2800,5523.31 ; v1@3958.47,5743.32 ccw(c3942.26,5727.11) 3942.26,5750.04 ccw(c3942.26,5772.98) v1@3958.47,5756.76 ; v1@3961.3,5746.15 ccw(c3951.91,5736.76) 3951.91,5750.04 ccw(c3951.91,5763.32) v1@3961.3,5753.93 ; v1(3965.19,5750.04) 3748.52,5750.04 3588.67,5909.89 3563.22,5935.34 3149.34,5935.34 3149,5935 3141.82,5935 3117.24,5910.43 2851,5644.19 2800,5593.18 v4(2800,5545) 2800,5523.31
ETH.E_RXC: U5.16 U8.B14 | length 4786.3
  Top Layer w4: v1(4102.86,5020.71) 4227.86,5020.71 v1(4265.19,4983.37) ; v1@4106.75,5016.82 cw(c4116.14,5007.43) 4116.14,5020.71 cw(c4116.14,5033.99) v1@4106.75,5024.6 ; v1@4109.57,5013.99 cw(c4125.79,4997.77) 4125.79,5020.71 cw(c4125.79,5043.64) v1@4109.57,5027.43 ; v1@4255.69,4983.37 ccw(c4232.76,4983.37) 4248.97,4999.59 ccw(c4265.19,5015.81) v1@4265.19,4992.87 ; v1@4259.69,4983.37 ccw(c4246.41,4983.37) 4255.8,4992.76 ccw(c4265.19,5002.15) v1@4265.19,4988.87 ; v1@5398.28,4833.28 cw(c5390.46,4825.46) 5401.52,4825.46 ; 5401.52,4808.67 cw(c5436.33,4808.67) v1@5411.72,4833.28 ; 5401.52,4818.33 cw(c5426.67,4818.33) v1@5408.89,4836.11 ; 5401.52,4827.99 cw(c5417.01,4827.99) v1@5406.06,4838.94 ; v1@5401.52,4830.37 5401.52,4750.71 5414.02,4738.21 5421.79,4738.21 5425.19,4734.81 5425.19,4720 5425.19,4710 5425.19,4662.47 cw(c5415.04,4662.47) 5422.22,4655.29 ; U8.B14@5409.69,4650.1 ccw(c5409.69,4667.83) 5422.22,4655.29 ; U8.B14@5417.03,4642.76 cw(c5434.75,4642.76) 5422.22,4655.29
  Bottom Layer w4: U5.16@2193.54,5440.79 2232.19,5440.79 2240.19,5432.79 2240.19,5340.19 2230.81,5330.81 2055.81,5330.81 2040.19,5315.19 2040.19,5061.36 2093.51,5008.04 3782,5008.04 3824,5050.04 4073.52,5050.04 v1(4102.86,5020.71) ; U5.16@2219.9,5437.96 cw(c2226.73,5431.13) 2226.73,5440.79 cw(c2226.73,5450.45) U5.16@2219.9,5443.62 ; v1@4093.36,5020.71 ccw(c4070.42,5020.71) 4086.64,5036.93 ccw(c4102.86,5053.14) v1@4102.86,5030.21 ; v1@4097.36,5020.71 ccw(c4084.08,5020.71) 4093.47,5030.1 ccw(c4102.86,5039.49) v1@4102.86,5026.21 ; v1(4265.19,4983.37) 4311.67,4983.37 4320,4991.71 4951.52,4991.71 4952.73,4990.5 4978.69,4964.54 5040.96,4964.54 5072.63,4932.87 5107.36,4932.87 5165.72,4991.23 5334.67,4991.23 5373.52,4952.37 5373.52,4871.48 v1(5405,4840) ; v1@4269.08,4979.49 cw(c4278.47,4970.1) 4278.47,4983.37 cw(c4278.47,4996.65) v1@4269.08,4987.26 ; v1@4271.91,4976.66 cw(c4288.13,4960.44) 4288.13,4983.37 cw(c4288.13,5006.31) v1@4271.91,4990.09 ; v1@5395.5,4840 ccw(c5372.56,4840) 5388.78,4856.22 ccw(c5405,4872.43) v1@5405,4849.5 ; v1@5399.5,4840 ccw(c5386.22,4840) 5395.61,4849.39 ccw(c5405,4858.78) v1@5405,4845.5
ETH.E_RXD0: U5.21 U8.C1 | length 4454
  Top Layer w4: v1@4740.19,4707.21 cw(c4740.19,4684.27) 4756.41,4700.49 cw(c4772.63,4716.71) v1@4749.69,4716.71 ; v1@4740.19,4711.21 cw(c4740.19,4697.93) 4749.58,4707.32 cw(c4758.97,4716.71) v1@4745.69,4716.71 ; v1(4740.19,4716.71) 4775.1,4681.79 4775.1,4613.9 4785.61,4603.39 4855.26,4603.39 4860,4603.39 4870,4603.39 U8.C1@4897.87,4603.39 ; U8.C1@4892.57,4598.08 ccw(c4879.77,4585.28) 4879.77,4603.39 ccw(c4879.77,4621.49) U8.C1@4892.57,4608.69 ; U8.C1@4892.68,4598.19 ccw(c4880.15,4585.66) 4880.15,4603.39 ccw(c4880.15,4621.11) U8.C1@4892.68,4608.58
  MidLayer1 w4: v1(4415.52,5741.37) 4462.54,5741.37 4631.86,5572.06 4631.86,5141.71 4739.94,5033.63 ; v1@4419.41,5737.49 cw(c4428.8,5728.1) 4428.8,5741.37 cw(c4428.8,5754.65) v1@4419.41,5745.26 ; v1@4422.24,5734.66 cw(c4438.46,5718.44) 4438.46,5741.37 cw(c4438.46,5764.31) v1@4422.24,5748.09 ; 4740,5033.69 4767,5006.69 4767,4743.52 v1(4740.19,4716.71) ; v1@4740.19,4722.21 ccw(c4740.19,4735.49) 4749.58,4726.1 ccw(c4758.97,4716.71) v1@4745.69,4716.71 ; v1@4740.19,4726.21 ccw(c4740.19,4749.14) 4756.41,4732.93 ccw(c4772.63,4716.71) v1@4749.69,4716.71
  MidLayer2 w4: v1@2133.47,5574.76 ccw(c2117.26,5590.98) 2140.19,5590.98 ccw(c2163.13,5590.98) v1@2146.91,5574.76 ; v1@2136.3,5571.93 ccw(c2126.91,5581.32) 2140.19,5581.32 ccw(c2153.47,5581.32) v1@2144.08,5571.93 ; v1(2140.19,5568.04) 2140.19,5759.19 2179,5798 2687,5798 2700,5785 2740,5785 2755,5800 4356.9,5800 4398.24,5758.66 v1(4415.52,5741.37) ; v1@4406.02,5741.37 ccw(c4383.09,5741.37) 4399.31,5757.59 ccw(c4415.52,5773.81) v1@4415.52,5750.87 ; v1@4410.02,5741.37 ccw(c4396.75,5741.37) 4406.14,5750.76 ccw(c4415.52,5760.15) v1@4415.52,5746.87
  Bottom Layer w4: v1@2133.96,5560.87 cw(c2122.11,5547.21) 2140.19,5547.21 ; v1@2136.58,5563.89 cw(c2129.72,5555.98) 2140.19,5555.98 cw(c2150.66,5555.98) v1@2143.8,5563.89 ; v1(2140.19,5568.04) 2140.19,5547.21 ; v1@2146.42,5560.87 ccw(c2158.27,5547.21) 2140.19,5547.21 ; U5.21@2167.19,5536.38 ccw(c2160.36,5529.56) 2160.36,5539.21 ccw(c2160.36,5548.87) U5.21@2167.19,5542.04 ; U5.21@2193.54,5539.21 2148.19,5539.21 2140.19,5547.21
ETH.E_RXD1: U5.20 U8.D2 | length 4065.9
  Top Layer w4: v1@4371.52,5584.21 cw(c4371.52,5561.27) 4387.74,5577.49 cw(c4403.96,5593.71) v1@4381.02,5593.71 ; v1@4371.52,5588.21 cw(c4371.52,5574.93) 4380.91,5584.32 cw(c4390.3,5593.71) v1@4377.02,5593.71 ; v1(4371.52,5593.71) 4443.93,5521.3 4455.23,5510 4599.27,5510 4623.52,5485.75 4623.52,5103.52 4610,5090 4610,5075 4623.84,5061.16 4623.84,4927.39 4685.31,4865.92 ; 4706.86,4844.37 4685.31,4865.92 ; 4685.31,4865.92 4714.86,4836.37 4714.86,4594.36 4729.69,4579.52 4860,4579.52 4870,4579.52 4917.53,4579.52 ; 4917.53,4579.52 cw(c4917.53,4569.37) 4924.71,4576.55 ; 4917.53,4579.52 cw(c4917.53,4569.37) 4924.71,4576.55 ; 4924.71,4576.55 cw(c4912.17,4564.02) 4929.9,4564.02 ccw(c4912.17,4564.02) 4924.71,4576.55 ; 4924.71,4576.55 ccw(c4937.24,4589.08) 4937.24,4571.36 cw(c4937.24,4589.08) 4924.71,4576.55
  MidLayer2 w4: v1(2147.86,5516.71) 2307.52,5516.71 2357.52,5566.71 2444.81,5566.71 2462.62,5548.9 2477.38,5548.9 2495.19,5566.71 3463.29,5566.71 3470,5560 3495,5560 3543.37,5608.37 4356.86,5608.37 v1(4371.52,5593.71) ; v1@2151.75,5512.82 cw(c2161.14,5503.43) 2161.14,5516.71 cw(c2161.14,5529.99) v1@2151.75,5520.6 ; v1@2154.57,5509.99 cw(c2170.79,5493.77) 2170.79,5516.71 cw(c2170.79,5539.64) v1@2154.57,5523.43
  Bottom Layer w4: v1(2147.86,5516.71) 2150.68,5519.53 U5.20@2193.54,5519.53 ; v1@2151.75,5512.82 cw(c2167.94,5496.62) U5.20@2167.94,5519.53 ; v1@2154.57,5509.99 cw(c2177.6,5486.96) U5.20@2177.6,5519.53 ; v1@2154.57,5523.43 ccw(c2163.98,5532.83) 2163.98,5519.53 ; U5.20@2167.19,5516.7 ccw(c2160.36,5509.87) 2160.36,5519.53 ccw(c2160.36,5529.18) U5.20@2167.19,5522.36
ETH.E_RXD2: U5.19 U8.D1 | length 3727.8
  Top Layer w4: v1@4665.19,4800.54 cw(c4665.19,4777.61) 4681.41,4793.82 cw(c4697.63,4810.04) v1@4674.69,4810.04 ; v1@4665.19,4804.54 cw(c4665.19,4791.26) 4674.58,4800.65 cw(c4683.97,4810.04) v1@4670.69,4810.04 ; v1(4665.19,4810.04) 4706.86,4768.37 4706.86,4591.04 4726.52,4571.37 4834.84,4571.37 4842.2,4564.02 4852,4564.02 4855.26,4564.02 4860,4564.02 4870,4564.02 U8.D1@4897.87,4564.02 ; U8.D1@4892.57,4558.71 ccw(c4879.77,4545.91) 4879.77,4564.02 ccw(c4879.77,4582.12) U8.D1@4892.57,4569.32 ; U8.D1@4892.68,4558.82 ccw(c4880.15,4546.29) 4880.15,4564.02 ccw(c4880.15,4581.74) U8.D1@4892.68,4569.21
  MidLayer1 w4: v1@2315.19,5548.87 cw(c2315.19,5525.94) 2331.41,5542.16 cw(c2347.63,5558.37) v1@2324.69,5558.37 ; v1@2315.19,5552.87 cw(c2315.19,5539.6) 2324.58,5548.99 cw(c2333.97,5558.37) v1@2320.69,5558.37 ; v1(2315.19,5558.37) 2340.86,5532.71 2513.77,5532.71 2621.06,5640 3667.63,5640 4040.92,5266.71 4348.52,5266.71 4665.19,4950.04 v1(4665.19,4810.04) ; v1@4658.47,4816.76 ccw(c4642.26,4832.98) 4665.19,4832.98 ccw(c4688.13,4832.98) v1@4671.91,4816.76 ; v1@4661.3,4813.93 ccw(c4651.91,4823.32) 4665.19,4823.32 ccw(c4678.47,4823.32) v1@4669.08,4813.93
  Bottom Layer w4: U5.19@2193.54,5499.84 2279.84,5499.84 2315.19,5535.19 v1(2315.19,5558.37) ; U5.19@2219.9,5497.01 cw(c2226.73,5490.19) 2226.73,5499.84 cw(c2226.73,5509.5) U5.19@2219.9,5502.67 ; v1@2308.47,5551.66 cw(c2292.26,5535.44) 2315.19,5535.44 cw(c2338.13,5535.44) v1@2321.91,5551.66 ; v1@2311.3,5554.49 cw(c2301.91,5545.1) 2315.19,5545.1 cw(c2328.47,5545.1) v1@2319.08,5554.49
ETH.E_RXD3: U5.18 U8.G5 | length 3861.3
  Top Layer w4: v3(5035.67,4465.59) U8.G5@5055.35,4445.91 ; U8.G5@5047.85,4445.91 ccw(c5029.75,4445.91) 5042.55,4458.71 ccw(c5055.35,4471.51) U8.G5@5055.35,4453.41 ; U8.G5@5048.01,4445.91 ccw(c5030.29,4445.91) 5042.82,4458.44 ccw(c5055.35,4470.97) U8.G5@5055.35,4453.25 ; 5048.47,4452.79 ccw(c5035.67,4439.98) 5035.67,4458.09 cw(c5035.67,4439.98) 5048.47,4452.79 ; 5048.47,4452.79 cw(c5061.28,4465.59) 5043.17,4465.59 ccw(c5061.28,4465.59) 5048.47,4452.79
  MidLayer1 w4: v1@2383.28,5443.28 cw(c2367.06,5427.06) 2390,5427.06 cw(c2412.93,5427.06) v1@2396.72,5443.28 ; v1@2386.11,5446.11 cw(c2376.72,5436.72) 2390,5436.72 cw(c2403.28,5436.72) v1@2393.89,5446.11 ; v1(2390,5450) 2390,5325 2398.29,5316.71 3595.52,5316.71 3795.02,5117.21 4424.11,5117.21 4483.86,5057.46 4483.86,5002.04 4481.86,5000.04 4481.86,4658.37 4490.19,4650.04 4531.86,4650.04 4565.19,4616.71 4645.54,4616.71 4687.21,4575.04 4711.19,4575.04 4799.38,4486.85 4805.13,4481.1 4860,4481.1 4870,4481.1 4918.62,4481.1 5012.16,4481.1 cw(c5012.16,4467.05) 5022.09,4476.99 ; v3@5028.2,4464.94 ccw(c5010.16,4463.36) 5021.8,4477.23 ccw(c5033.44,4491.1) v3@5035.02,4473.06
  Bottom Layer w4: U5.18@2193.54,5480.16 2248.03,5480.16 2259.58,5491.71 2348.29,5491.71 v1(2390,5450) ; U5.18@2219.9,5477.33 cw(c2226.73,5470.5) 2226.73,5480.16 cw(c2226.73,5489.81) U5.18@2219.9,5482.99 ; v1@2380.5,5450 ccw(c2357.56,5450) 2373.78,5466.22 ccw(c2390,5482.43) v1@2390,5459.5 ; v1@2384.5,5450 ccw(c2371.22,5450) 2380.61,5459.39 ccw(c2390,5468.78) v1@2390,5455.5
ETH.E_RXDV: U5.22 U8.C2 | length 4057
  Top Layer w4: v1(4807.86,4626.04) 4815,4618.89 4860,4618.89 ; 4856.86,4618.89 4855.26,4618.89 4860,4618.89 ; 4860,4618.89 4870,4618.89 4917.53,4618.89 ; 4917.53,4618.89 cw(c4917.53,4608.74) 4924.71,4615.92 ; 4917.53,4618.89 cw(c4917.53,4608.74) 4924.71,4615.92 ; 4924.71,4615.92 cw(c4912.17,4603.39) 4929.9,4603.39 ccw(c4912.17,4603.39) 4924.71,4615.92 ; 4924.71,4615.92 ccw(c4937.24,4628.45) 4937.24,4610.73 cw(c4937.24,4628.45) 4924.71,4615.92
  MidLayer1 w4: v1@2445,5598.9 v1(2445,5595) 2498,5648 3829.82,5648 3981.86,5800.04 4415.19,5800.04 4640.19,5575.04 4640.19,5144.81 4775,5010 4775,4658.9 v1(4807.86,4626.04) v1@4805.86,4626.04 ; v1@2445,5600.5 ccw(c2445,5613.78) 2454.39,5604.39 ccw(c2463.78,5595) v1@2450.5,5595 ; v1@2445,5604.5 ccw(c2445,5627.43) 2461.22,5611.22 ccw(c2477.43,5595) v1@2454.5,5595 ; v1@4798.36,4626.04 ccw(c4775.42,4626.04) 4791.64,4642.26 ccw(c4807.86,4658.48) v1@4807.86,4635.54 ; v1@4802.36,4626.04 ccw(c4789.08,4626.04) 4798.47,4635.43 ccw(c4807.86,4644.82) v1@4807.86,4631.54
  Bottom Layer w4: U5.22@2193.54,5558.37 2290.19,5558.37 2313.52,5581.71 2360.79,5581.71 2375.79,5566.71 2416.71,5566.71 v1(2445,5595) v1@2445,5598.9 ; U5.22@2219.9,5556.07 cw(c2225.47,5550.5) 2225.47,5558.37 ; U5.22@2219.9,5561.73 ccw(c2227.99,5569.82) 2227.99,5558.37 ; v1@2435.5,5595 cw(c2412.56,5595) 2428.78,5578.78 cw(c2445,5562.56) v1@2445,5585.5 ; v1@2439.5,5595 cw(c2426.22,5595) 2435.61,5585.61 cw(c2445,5576.22) v1@2445,5589.5
ETH.E_RXER: U6.14 U8.A7 | length 2792.6
  Top Layer w4: v1@5076.47,4951.66 cw(c5060.26,4935.44) 5083.19,4935.44 cw(c5106.13,4935.44) v1@5089.91,4951.66 ; v1@5079.3,4954.49 cw(c5069.91,4945.1) 5083.19,4945.1 cw(c5096.47,4945.1) v1@5087.08,4954.49 ; v1(5083.19,4958.37) 5083.19,4918.04 5123.52,4877.71 5123.52,4867.98 5134.09,4857.41 5134.09,4724.74 5134.09,4720 5134.09,4710 U8.A7@5134.09,4682.13 ; U8.A7@5128.79,4687.43 ccw(c5115.99,4700.23) 5134.09,4700.23 ccw(c5152.2,4700.23) U8.A7@5139.4,4687.43 ; 5134.09,4699.85 cw(c5116.37,4699.85) 5128.9,4687.32 ccw(c5116.37,4699.85) 5134.09,4699.85 ; 5134.09,4699.85 ccw(c5151.82,4699.85) 5139.29,4687.32 cw(c5151.82,4699.85) 5134.09,4699.85
  Bottom Layer w4: U6.14@3341.06,5546.61 3483.39,5546.61 3550.61,5479.39 3550.61,5461.09 3556.72,5454.98 3728.47,5454.98 3740.19,5466.71 3931.86,5466.71 3956.86,5441.71 4006.86,5441.71 4023.86,5458.71 4322.85,5458.71 4331.52,5450.04 4581.86,5450.04 4673.52,5541.71 4723.52,5541.71 4973.52,5291.71 4973.52,4992.79 4985.77,4980.54 5061.02,4980.54 v1(5083.19,4958.37) ; U6.14@3379.38,5541.76 cw(c3391.08,5530.06) 3391.08,5546.61 cw(c3391.09,5563.17) U6.14@3379.38,5551.46 ; v1@5073.69,4958.37 ccw(c5050.76,4958.37) 5066.97,4974.59 ccw(c5083.19,4990.81) v1@5083.19,4967.87 ; v1@5077.69,4958.37 ccw(c5064.41,4958.37) 5073.8,4967.76 ccw(c5083.19,4977.15) v1@5083.19,4963.87
ETH.E_TXC: U5.7 U8.H4 | length 4647.4
  Top Layer w4: v3(4996.3,4426.22) U8.H4@5015.98,4406.54 ; U8.H4@5008.48,4406.54 ccw(c4990.38,4406.54) 5003.18,4419.34 ccw(c5015.98,4432.14) U8.H4@5015.98,4414.04 ; U8.H4@5008.64,4406.54 ccw(c4990.92,4406.54) 5003.45,4419.07 ccw(c5015.98,4431.6) U8.H4@5015.98,4413.88 ; 5009.1,4413.42 cw(c5021.91,4426.22) 5003.8,4426.22 ccw(c5021.91,4426.22) 5009.1,4413.42 ; 5009.1,4413.42 ccw(c4996.3,4400.61) 4996.3,4418.72 cw(c4996.3,4400.61) 5009.1,4413.42
  MidLayer1 w4: v1(1815.19,5066.71) 1840.19,5091.71 1873.52,5091.71 1890.19,5075.04 1890.69,5074.54 3453.19,5074.54 3488.65,5110 3549.88,5110 3576.5,5083.37 4013.13,5083.37 4173.69,4922.81 4173.69,4908.46 4257.61,4824.54 4259.73,4824.54 4340,4744.27 4340,4718.13 4518.13,4540 4608.56,4540 4715.19,4433.37 4779.22,4433.37 4786.37,4426.22 4799.29,4426.22 4860,4426.22 4870,4426.22 4918.62,4426.22 v3(4996.3,4426.22) ; v1@1815.19,5072.21 ccw(c1815.19,5085.49) 1824.58,5076.1 ccw(c1833.97,5066.71) v1@1820.69,5066.71 ; v1@1815.19,5076.21 ccw(c1815.19,5099.14) 1831.41,5082.93 ccw(c1847.63,5066.71) v1@1824.69,5066.71 ; v3@4991,4420.92 ccw(c4978.19,4408.11) 4978.19,4426.22 ccw(c4978.19,4444.33) v3@4991,4431.52 ; v3@4991.11,4421.03 ccw(c4978.57,4408.49) 4978.57,4426.22 ccw(c4978.57,4443.95) v3@4991.11,4431.41
  MidLayer2 w4: v1@1808.47,5073.43 ccw(c1792.26,5089.64) 1815.19,5089.64 ccw(c1838.13,5089.64) v1@1821.91,5073.43 ; v1@1811.3,5070.6 ccw(c1801.91,5079.99) 1815.19,5079.99 ccw(c1828.47,5079.99) v1@1819.08,5070.6 ; v1(1815.19,5066.71) 1815.19,5200.04 1831.86,5216.71 1915.19,5216.71 1973.52,5275.04 1976.29,5277.81 2348.75,5277.81 v1(2351.52,5275.04) ; 2321.9,5277.81 cw(c2321.9,5245.42) v1@2344.81,5268.32 ; 2331.56,5277.81 cw(c2331.56,5255.07) v1@2347.64,5271.15 ; 2335.28,5277.81 ccw(c2335.28,5291.29) v1@2344.81,5281.76
  Bottom Layer w4: U5.7@2348.59,5295.98 cw(c2344.81,5291.04) 2351.02,5291.04 ; U5.7@2351.02,5322.68 2351.02,5291.04 ; v1(2351.52,5275.04) 2351.52,5290.54 2351.02,5291.04 ; U5.7@2353.46,5295.98 ccw(c2357.24,5291.04) 2351.02,5291.04
ETH.E_TXD0: R45.1 U5.6 U8.F4 | length 4496.3
  Top Layer w4: v3(4996.3,4504.96) U8.F4@5015.98,4485.28 ; U8.F4@5008.48,4485.28 ccw(c4990.38,4485.28) 5003.18,4498.08 ccw(c5015.98,4510.88) U8.F4@5015.98,4492.78 ; U8.F4@5008.64,4485.28 ccw(c4990.92,4485.28) 5003.45,4497.81 ccw(c5015.98,4510.34) U8.F4@5015.98,4492.62 ; 5009.1,4492.16 cw(c5021.91,4504.96) 5003.8,4504.96 ccw(c5021.91,4504.96) 5009.1,4492.16 ; 5009.1,4492.16 ccw(c4996.3,4479.35) 4996.3,4497.46 cw(c4996.3,4479.35) 5009.1,4492.16
  MidLayer1 w4: v1(2140.19,5208.37) 2173.52,5241.71 2231.86,5241.71 2290.19,5183.37 2348.52,5183.37 2373.52,5208.37 2373.52,5426.48 2365,5435 2365,5475 2375,5485 2405,5485 2420,5470 2420,5445 2450,5415 2780,5415 2860.72,5334.28 3600.6,5334.28 3801.67,5133.21 4435.02,5133.21 4615.19,4953.04 4615.19,4726.37 4706.86,4634.71 4706.86,4606.04 4801.8,4511.1 4807.94,4504.96 4860,4504.96 4870,4504.96 4918.62,4504.96 v3(4996.3,4504.96) ; v1@2140.19,5213.87 ccw(c2140.19,5227.15) 2149.58,5217.76 ccw(c2158.97,5208.37) v1@2145.69,5208.37 ; v1@2140.19,5217.87 ccw(c2140.19,5240.81) 2156.41,5224.59 ccw(c2172.63,5208.37) v1@2149.69,5208.37 ; v3@4991.11,4499.77 ccw(c4978.57,4487.23) 4978.57,4504.96 ccw(c4978.57,4522.69) v3@4991.11,4510.15 ; 4978.19,4504.96 cw(c4978.19,4486.85) 4991,4499.66 ccw(c4978.19,4486.85) 4978.19,4504.96 ; 4978.19,4504.96 ccw(c4978.19,4523.07) 4991,4510.26 cw(c4978.19,4523.07) 4978.19,4504.96
  Bottom Layer w4: v1(2140.19,5208.37) R45.1@2170,5208.37 ; v1@2141.71,5208.37 cw(c2141.71,5178.39) R45.1@2162.92,5199.59 ; v1@2144.08,5204.49 cw(c2153.47,5195.1) 2153.47,5208.37 cw(c2153.47,5221.65) v1@2144.08,5212.26 ; v1@2146.91,5201.66 cw(c2163.13,5185.44) 2163.13,5208.37 cw(c2163.13,5231.31) v1@2146.91,5215.09 ; v1@2151.37,5208.37 cw(c2151.37,5188.04) R45.1@2165.75,5202.42 ; 2152.31,5208.37 ccw(c2152.31,5223.38) R45.1@2162.92,5212.77 ; R45.1@2166.51,5214.82 ccw(c2164.41,5220) 2170,5220 ccw(c2175.59,5220) R45.1@2173.49,5214.82 ; R45.1@2170,5206.18 2170,5220 2180,5230 2245,5230 2249.19,5234.19 2307.38,5234.19 2322.9,5249.71 2353.71,5249.71 2370.71,5266.71 U5.6@2370.71,5322.68 ; U5.6@2367.88,5296.32 cw(c2361.05,5289.49) 2370.71,5289.49 cw(c2380.36,5289.49) U5.6@2373.54,5296.32
ETH.E_TXD1: R44.1 U5.5 U8.E1 | length 3975.6
  Top Layer w4: v1@4459.03,5009.48 cw(c4447.64,4996.12) 4465.19,4996.12 ; v1@4461.62,5012.52 cw(c4455.03,5004.79) 4465.19,5004.79 cw(c4475.35,5004.79) v1@4468.76,5012.52 ; v1(4465.19,5016.71) 4465.19,4996.12 ; v1@4471.35,5009.48 ccw(c4482.74,4996.12) 4465.19,4996.12 ; U8.E1@4892.57,4519.34 ccw(c4879.77,4506.54) 4879.77,4524.65 ccw(c4879.77,4542.75) U8.E1@4892.57,4529.95 ; U8.E1@4892.68,4519.45 ccw(c4880.15,4506.92) 4880.15,4524.65 ccw(c4880.15,4542.37) U8.E1@4892.68,4529.84 ; U8.E1@4897.87,4524.65 4870,4524.65 4860,4524.65 4842.13,4524.65 4835.19,4517.71 4781.01,4517.71 4778.01,4520.71 4703.83,4520.71 4698.83,4515.71 4673.52,4515.71 4665.19,4524.04 4665.19,4566.71 4648.52,4583.37 4648.52,4722.06 4556.86,4813.73 4556.86,4904.46 4465.19,4996.12
  MidLayer1 w4: v1@2198.52,5198.87 cw(c2198.52,5175.94) 2214.74,5192.16 cw(c2230.96,5208.37) v1@2208.02,5208.37 ; v1@2198.52,5202.87 cw(c2198.52,5189.6) 2207.91,5198.99 cw(c2217.3,5208.37) v1@2204.02,5208.37 ; v1(2198.52,5208.37) 2231.86,5175.04 2373.52,5175.04 2506.86,5308.37 3141.63,5308.37 ; 3141.29,5308.71 3141.63,5308.37 ; v1@4458.47,5023.43 ccw(c4442.26,5039.64) 4465.19,5039.64 ccw(c4488.13,5039.64) v1@4471.91,5023.43 ; v1@4461.3,5020.6 ccw(c4451.91,5029.99) 4465.19,5029.99 ccw(c4478.47,5029.99) v1@4469.08,5020.6 ; v1(4465.19,5016.71) 4465.19,5064.81 4420.79,5109.21 3791.71,5109.21 3592.54,5308.37 3141.63,5308.37
  Bottom Layer w4: v1(2198.52,5208.37) 2233.81,5208.37 R44.1@2236,5206.18 ; v1@2202.41,5204.49 cw(c2211.8,5195.1) 2211.8,5208.37 cw(c2211.8,5221.65) v1@2202.41,5212.26 ; v1@2205.24,5201.66 cw(c2221.46,5185.44) 2221.46,5208.37 cw(c2221.46,5231.31) v1@2205.24,5215.09 ; v1@2207.71,5208.37 cw(c2207.71,5178.39) R44.1@2228.92,5199.59 ; 2217.37,5208.37 cw(c2217.37,5188.04) R44.1@2231.75,5202.42 ; 2218.31,5208.37 ccw(c2218.31,5223.38) R44.1@2228.92,5212.77 ; R44.1@2236,5208.37 R44.1@2236,5206.18 ; R44.1@2236.49,5211.5 ccw(c2236.49,5223.15) R44.1@2244.73,5214.91 ; R44.1@2236.49,5215.5 ccw(c2236.49,5236.81) 2251.56,5221.74 ; R44.1@2241.81,5206.18 cw(c2255.84,5206.18) R44.1@2245.92,5216.1 ; R44.1@2245.81,5206.18 cw(c2269.5,5206.18) 2252.75,5222.93 ; U5.5@2387.57,5296.32 cw(c2380.74,5289.49) 2390.39,5289.49 cw(c2400.05,5289.49) U5.5@2393.22,5296.32 ; U5.5@2390.39,5322.68 2390.39,5267.1 2365,5241.71 2326.21,5241.71 2310.69,5226.19 2256.01,5226.19 R44.1@2236,5206.18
